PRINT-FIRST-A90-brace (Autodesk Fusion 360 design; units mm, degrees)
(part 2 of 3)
sketch "B Facet 180 Triangle 3" plane through (0, -75, 0) normal (0, -1, 0) x axis (-1, 0, 0)
  line L1 (60.9665, 27.066) -> (-2.067, -27.066)
  line L2 (124, -27.066) -> (60.9665, 27.066)
  line L3 (-2.067, -27.066) -> (124, -27.066)
  line L4 (60.9665, 21.7934) -> (8.7304, -23.066)
  line L5 (113.2026, -23.066) -> (60.9665, 21.7934)
  line L6 (8.7304, -23.066) -> (113.2026, -23.066)
  point P1 (0, 0)
  point P2 (-2.067, -27.066)
  point P3 (60.9665, 27.066)
  point P4 (124, -27.066)
  dimension "d477" distance P1 P2 = 2.067 (= "Linear Dimension-2")
  dimension "d478" distance P1 P2 = 27.066 (= "Linear Dimension-3")
  dimension "d479" distance P1 P3 = 60.9665 (= "Linear Dimension-4")
  dimension "d480" distance P1 P3 = 27.066 (= "Linear Dimension-5")
  dimension "d481" distance P1 P4 = 124 (= "Linear Dimension-6")
  dimension "d482" distance P1 P4 = 27.066 (= "Linear Dimension-7")
  dimension "d483" = 4 (= "memberWidth / 2")
extrude "Extrude14" cut sketch "B Facet 180 Triangle 3" profile of L5 L6 L4 against normal blind 4.7 (magnitude of "-( wall + 0.2 mm )")
sketch "B Facet 180 Triangle 4" plane through (0, -75, 0) normal (0, -1, 0) x axis (-1, 0, 0)
  line L1 (124, -27.066) -> (60.9665, 27.066)
  line L2 (124, 27.066) -> (124, -27.066)
  line L3 (60.9665, 27.066) -> (124, 27.066)
  line L4 (120, -18.3583) -> (71.7639, 23.066)
  line L5 (120, 23.066) -> (120, -18.3583)
  line L6 (71.7639, 23.066) -> (120, 23.066)
  point P1 (0, 0)
  point P2 (60.9665, 27.066)
  point P3 (124, -27.066)
  point P4 (124, 27.066)
  dimension "d486" distance P1 P2 = 60.9665 (= "Linear Dimension-2")
  dimension "d487" distance P1 P2 = 27.066 (= "Linear Dimension-3")
  dimension "d488" distance P1 P3 = 124 (= "Linear Dimension-4")
  dimension "d489" distance P1 P3 = 27.066 (= "Linear Dimension-5")
  dimension "d490" distance P1 P4 = 124 (= "Linear Dimension-6")
  dimension "d491" distance P1 P4 = 27.066 (= "Linear Dimension-7")
  dimension "d492" = -4 (= "-memberWidth / 2")
extrude "Extrude15" cut sketch "B Facet 180 Triangle 4" profile of L5 L6 L4 against normal blind 4.7 (magnitude of "-( wall + 0.2 mm )")
fillet "Fillet5" radius 1.5 (= "apertureRadius")
work_plane "WorkPlane11" RotateAngle 135 ExtraOffset 0
work_plane "WorkPlane12" AlongDistance 75 (= "bodyWidth / 2") ExtraOffset 0
sketch "B Facet 225 Triangle 1" plane through (0, -53.033, -53.033) normal (0, -0.7071, -0.7071) x axis (1, 0, 0)
  line L1 (23.9949, -27.066) -> (62.2721, 27.066)
  line L2 (0.1814, 27.066) -> (23.9949, -27.066)
  line L3 (62.2721, 27.066) -> (0.1814, 27.066)
  line L4 (24.81, -18.9852) -> (54.5447, 23.066)
  line L5 (6.311, 23.066) -> (24.81, -18.9852)
  line L6 (54.5447, 23.066) -> (6.311, 23.066)
  point P1 (0, 0)
  point P2 (62.2721, 27.066)
  point P3 (23.9949, -27.066)
  point P4 (0.1814, 27.066)
  dimension "d501" distance P1 P2 = 62.2721 (= "Linear Dimension-2")
  dimension "d502" distance P1 P2 = 27.066 (= "Linear Dimension-3")
  dimension "d503" distance P1 P3 = 23.9949 (= "Linear Dimension-4")
  dimension "d504" distance P1 P3 = 27.066 (= "Linear Dimension-5")
  dimension "d505" distance P1 P4 = 0.1814 (= "Linear Dimension-6")
  dimension "d506" distance P1 P4 = 27.066 (= "Linear Dimension-7")
  dimension "d507" = 4 (= "memberWidth / 2")
extrude "Extrude16" cut sketch "B Facet 225 Triangle 1" profile of L5 L6 L4 against normal blind 4.7 (magnitude of "-( wall + 0.2 mm )")
sketch "B Facet 225 Triangle 2" plane through (0, -53.033, -53.033) normal (0, -0.7071, -0.7071) x axis (1, 0, 0)
  line L1 (0.1814, 27.066) -> (23.9949, -27.066)
  line L2 (-74.6684, -27.066) -> (0.1814, 27.066)
  line L3 (23.9949, -27.066) -> (-74.6684, -27.066)
  line L4 (-1.4863, 20.9235) -> (17.8653, -23.066)
  line L5 (-62.3117, -23.066) -> (-1.4863, 20.9235)
  line L6 (17.8653, -23.066) -> (-62.3117, -23.066)
  point P1 (0, 0)
  point P2 (23.9949, -27.066)
  point P3 (0.1814, 27.066)
  point P4 (-74.6684, -27.066)
  dimension "d510" distance P1 P2 = 23.9949 (= "Linear Dimension-2")
  dimension "d511" distance P1 P2 = 27.066 (= "Linear Dimension-3")
  dimension "d512" distance P1 P3 = 0.1814 (= "Linear Dimension-4")
  dimension "d513" distance P1 P3 = 27.066 (= "Linear Dimension-5")
  dimension "d514" distance P1 P4 = 74.6684 (= "Linear Dimension-6")
  dimension "d515" distance P1 P4 = 27.066 (= "Linear Dimension-7")
  dimension "d516" = -4 (= "-memberWidth / 2")
extrude "Extrude17" cut sketch "B Facet 225 Triangle 2" profile of L5 L6 L4 against normal blind 4.7 (magnitude of "-( wall + 0.2 mm )")
sketch "B Facet 225 Triangle 3" plane through (0, -53.033, -53.033) normal (0, -0.7071, -0.7071) x axis (1, 0, 0)
  line L1 (-74.6684, -27.066) -> (0.1814, 27.066)
  line L2 (-124, 27.066) -> (-74.6684, -27.066)
  line L3 (0.1814, 27.066) -> (-124, 27.066)
  line L4 (-74.1179, -21.7315) -> (-12.1753, 23.066)
  line L5 (-114.9429, 23.066) -> (-74.1179, -21.7315)
  line L6 (-12.1753, 23.066) -> (-114.9429, 23.066)
  point P1 (0, 0)
  point P2 (0.1814, 27.066)
  point P3 (-74.6684, -27.066)
  point P4 (-124, 27.066)
  dimension "d519" distance P1 P2 = 0.1814 (= "Linear Dimension-2")
  dimension "d520" distance P1 P2 = 27.066 (= "Linear Dimension-3")
  dimension "d521" distance P1 P3 = 74.6684 (= "Linear Dimension-4")
  dimension "d522" distance P1 P3 = 27.066 (= "Linear Dimension-5")
  dimension "d523" distance P1 P4 = 124 (= "Linear Dimension-6")
  dimension "d524" distance P1 P4 = 27.066 (= "Linear Dimension-7")
  dimension "d525" = 4 (= "memberWidth / 2")
extrude "Extrude18" cut sketch "B Facet 225 Triangle 3" profile of L5 L6 L4 against normal blind 4.7 (magnitude of "-( wall + 0.2 mm )")
sketch "B Facet 225 Triangle 4" plane through (0, -53.033, -53.033) normal (0, -0.7071, -0.7071) x axis (1, 0, 0)
  line L1 (-124, 27.066) -> (-74.6684, -27.066)
  line L2 (-124, -27.066) -> (-124, 27.066)
  line L3 (-74.6684, -27.066) -> (-124, -27.066)
  line L4 (-120, 16.7383) -> (-83.7255, -23.066)
  line L5 (-120, -23.066) -> (-120, 16.7383)
  line L6 (-83.7255, -23.066) -> (-120, -23.066)
  point P1 (0, 0)
  point P2 (-74.6684, -27.066)
  point P3 (-124, 27.066)
  point P4 (-124, -27.066)
  dimension "d528" distance P1 P2 = 74.6684 (= "Linear Dimension-2")
  dimension "d529" distance P1 P2 = 27.066 (= "Linear Dimension-3")
  dimension "d530" distance P1 P3 = 124 (= "Linear Dimension-4")
  dimension "d531" distance P1 P3 = 27.066 (= "Linear Dimension-5")
  dimension "d532" distance P1 P4 = 124 (= "Linear Dimension-6")
  dimension "d533" distance P1 P4 = 27.066 (= "Linear Dimension-7")
  dimension "d534" = -4 (= "-memberWidth / 2")
extrude "Extrude19" cut sketch "B Facet 225 Triangle 4" profile of L5 L6 L4 against normal blind 4.7 (magnitude of "-( wall + 0.2 mm )")
fillet "Fillet6" radius 1.5 (= "apertureRadius")
work_plane "WorkPlane13" RotateAngle 180 ExtraOffset 0
work_plane "WorkPlane14" AlongDistance 75 (= "bodyWidth / 2") ExtraOffset 0
sketch "B Facet 270 Triangle 1" plane through (0, 0, -75) normal (0, 0, -1) x axis (-1, 0, 0)
  line L1 (36.9655, 27.066) -> (-17.1665, -27.066)
  line L2 (53.4167, -27.066) -> (36.9655, 27.066)
  line L3 (-17.1665, -27.066) -> (53.4167, -27.066)
  line L4 (35.0777, 19.5214) -> (-7.5097, -23.066)
  line L5 (48.0205, -23.066) -> (35.0777, 19.5214)
  line L6 (-7.5097, -23.066) -> (48.0205, -23.066)
  point P1 (0, 0)
  point P2 (-17.1665, -27.066)
  point P3 (36.9655, 27.066)
  point P4 (53.4167, -27.066)
  dimension "d543" distance P1 P2 = 17.1665 (= "Linear Dimension-2")
  dimension "d544" distance P1 P2 = 27.066 (= "Linear Dimension-3")
  dimension "d545" distance P1 P3 = 36.9655 (= "Linear Dimension-4")
  dimension "d546" distance P1 P3 = 27.066 (= "Linear Dimension-5")
  dimension "d547" distance P1 P4 = 53.4167 (= "Linear Dimension-6")
  dimension "d548" distance P1 P4 = 27.066 (= "Linear Dimension-7")
  dimension "d549" = 4 (= "memberWidth / 2")
extrude "Extrude20" cut sketch "B Facet 270 Triangle 1" profile of L5 L6 L4 against normal blind 4.7 (magnitude of "-( wall + 0.2 mm )")
sketch "B Facet 270 Triangle 2" plane through (0, 0, -75) normal (0, 0, -1) x axis (-1, 0, 0)
  line L1 (53.4167, -27.066) -> (36.9655, 27.066)
  line L2 (124, 27.066) -> (53.4167, -27.066)
  line L3 (36.9655, 27.066) -> (124, 27.066)
  line L4 (55.5648, -20.3777) -> (42.3618, 23.066)
  line L5 (112.2115, 23.066) -> (55.5648, -20.3777)
  line L6 (42.3618, 23.066) -> (112.2115, 23.066)
  point P1 (0, 0)
  point P2 (36.9655, 27.066)
  point P3 (53.4167, -27.066)
  point P4 (124, 27.066)
  dimension "d552" distance P1 P2 = 36.9655 (= "Linear Dimension-2")
  dimension "d553" distance P1 P2 = 27.066 (= "Linear Dimension-3")
  dimension "d554" distance P1 P3 = 53.4167 (= "Linear Dimension-4")
  dimension "d555" distance P1 P3 = 27.066 (= "Linear Dimension-5")
  dimension "d556" distance P1 P4 = 124 (= "Linear Dimension-6")
  dimension "d557" distance P1 P4 = 27.066 (= "Linear Dimension-7")
  dimension "d558" = -4 (= "-memberWidth / 2")
extrude "Extrude21" cut sketch "B Facet 270 Triangle 2" profile of L5 L6 L4 against normal blind 4.7 (magnitude of "-( wall + 0.2 mm )")
sketch "B Facet 270 Triangle 3" plane through (0, 0, -75) normal (0, 0, -1) x axis (-1, 0, 0)
  line L1 (124, 27.066) -> (53.4167, -27.066)
  line L2 (124, -27.066) -> (124, 27.066)
  line L3 (53.4167, -27.066) -> (124, -27.066)
  line L4 (120, 18.9574) -> (65.2053, -23.066)
  line L5 (120, -23.066) -> (120, 18.9574)
  line L6 (65.2053, -23.066) -> (120, -23.066)
  point P1 (0, 0)
  point P2 (53.4167, -27.066)
  point P3 (124, 27.066)
  point P4 (124, -27.066)
  dimension "d561" distance P1 P2 = 53.4167 (= "Linear Dimension-2")
  dimension "d562" distance P1 P2 = 27.066 (= "Linear Dimension-3")
  dimension "d563" distance P1 P3 = 124 (= "Linear Dimension-4")
  dimension "d564" distance P1 P3 = 27.066 (= "Linear Dimension-5")
  dimension "d565" distance P1 P4 = 124 (= "Linear Dimension-6")
  dimension "d566" distance P1 P4 = 27.066 (= "Linear Dimension-7")
  dimension "d567" = 4 (= "memberWidth / 2")
extrude "Extrude22" cut sketch "B Facet 270 Triangle 3" profile of L5 L6 L4 against normal blind 4.7 (magnitude of "-( wall + 0.2 mm )")
fillet "Fillet7" radius 1.5 (= "apertureRadius")
work_plane "WorkPlane15" RotateAngle 225 ExtraOffset 0
work_plane "WorkPlane16" AlongDistance 75 (= "bodyWidth / 2") ExtraOffset 0
sketch "B Facet 315 Triangle 1" plane through (0, 53.033, -53.033) normal (0, 0.7071, -0.7071) x axis (1, 0, 0)
  line L1 (-82.0711, -27.066) -> (-43.7939, 27.066)
  line L2 (-124, 27.066) -> (-82.0711, -27.066)
  line L3 (-43.7939, 27.066) -> (-124, 27.066)
  line L4 (-82.2175, -20.3449) -> (-51.5213, 23.066)
  line L5 (-115.8422, 23.066) -> (-82.2175, -20.3449)
  line L6 (-51.5213, 23.066) -> (-115.8422, 23.066)
  point P1 (0, 0)
  point P2 (-43.7939, 27.066)
  point P3 (-82.0711, -27.066)
  point P4 (-124, 27.066)
  dimension "d576" distance P1 P2 = 43.7939 (= "Linear Dimension-2")
  dimension "d577" distance P1 P2 = 27.066 (= "Linear Dimension-3")
  dimension "d578" distance P1 P3 = 82.0711 (= "Linear Dimension-4")
  dimension "d579" distance P1 P3 = 27.066 (= "Linear Dimension-5")
  dimension "d580" distance P1 P4 = 124 (= "Linear Dimension-6")
  dimension "d581" distance P1 P4 = 27.066 (= "Linear Dimension-7")
  dimension "d582" = 4 (= "memberWidth / 2")
extrude "Extrude23" cut sketch "B Facet 315 Triangle 1" profile of L5 L6 L4 against normal blind 4.7 (magnitude of "-( wall + 0.2 mm )")
sketch "B Facet 315 Triangle 2" plane through (0, 53.033, -53.033) normal (0, 0.7071, -0.7071) x axis (1, 0, 0)
  line L1 (-124, 27.066) -> (-82.0711, -27.066)
  line L2 (-124, -27.066) -> (-124, 27.066)
  line L3 (-82.0711, -27.066) -> (-124, -27.066)
  line L4 (-120, 15.3697) -> (-90.2289, -23.066)
  line L5 (-120, -23.066) -> (-120, 15.3697)
  line L6 (-90.2289, -23.066) -> (-120, -23.066)
  point P1 (0, 0)
  point P2 (-82.0711, -27.066)
  point P3 (-124, 27.066)
  point P4 (-124, -27.066)
  dimension "d585" distance P1 P2 = 82.0711 (= "Linear Dimension-2")
  dimension "d586" distance P1 P2 = 27.066 (= "Linear Dimension-3")
  dimension "d587" distance P1 P3 = 124 (= "Linear Dimension-4")
  dimension "d588" distance P1 P3 = 27.066 (= "Linear Dimension-5")
  dimension "d589" distance P1 P4 = 124 (= "Linear Dimension-6")
  dimension "d590" distance P1 P4 = 27.066 (= "Linear Dimension-7")
  dimension "d591" = -4 (= "-memberWidth / 2")
extrude "Extrude24" cut sketch "B Facet 315 Triangle 2" profile of L5 L6 L4 against normal blind 4.7 (magnitude of "-( wall + 0.2 mm )")
fillet "Fillet8" radius 1.5 (= "apertureRadius")
work_plane "WorkPlane17" AlongDistance 0.5 (= "qFront") ExtraOffset 0
sketch "A Central Carrier sketch" plane through (0.3536, 0.3536, 0) normal (0.7071, 0.7071, 0) x axis (0, 0, 1)
  circle C1 centre (0, 0) radius 26
  dimension "d598" diameter C1 = 52 (= "carrierOD")
extrude "Extrude25" new body sketch "A Central Carrier sketch" along normal blind 18 (= "spokeDepth")
work_plane "WorkPlane18" AlongDistance 0.5 (= "qFront") ExtraOffset 0
sketch "A Spoke 1 Profile" plane through (0.3536, 0.3536, 0) normal (0.7071, 0.7071, 0) x axis (0, 0, 1)
  line L1 (37.3643, -145.3579) -> (-4.7984, -1.4054)
  line L2 (46.9611, -142.547) -> (37.3643, -145.3579)
  line L3 (4.7984, 1.4054) -> (46.9611, -142.547)
  line L4 (-4.7984, -1.4054) -> (4.7984, 1.4054)
  point P1 (0, 0)
  point P2 (-4.7984, -1.4054)
  point P3 (37.3643, -145.3579)
  point P4 (46.9611, -142.547)
  point P5 (4.7984, 1.4054)
  dimension "d603" distance P1 P2 = 4.7984 (= "Linear Dimension-2")
  dimension "d604" distance P1 P2 = 1.4054 (= "Linear Dimension-3")
  dimension "d605" distance P1 P3 = 37.3643 (= "Linear Dimension-4")
  dimension "d606" distance P1 P3 = 145.3579 (= "Linear Dimension-5")
  dimension "d607" distance P1 P4 = 46.9611 (= "Linear Dimension-6")
  dimension "d608" distance P1 P4 = 142.547 (= "Linear Dimension-7")
  dimension "d609" distance P1 P5 = 4.7984 (= "Linear Dimension-8")
  dimension "d610" distance P1 P5 = 1.4054 (= "Linear Dimension-9")
extrude "Extrude26" add sketch "A Spoke 1 Profile" along normal blind 18 (= "spokeDepth")
sketch "A Spoke 2 Profile" plane through (0.3536, 0.3536, 0) normal (0.7071, 0.7071, 0) x axis (0, 0, 1)
  line L1 (126.9012, -80.1317) -> (-2.5272, -4.3143)
  line L2 (131.9557, -71.5031) -> (126.9012, -80.1317)
  line L3 (2.5272, 4.3143) -> (131.9557, -71.5031)
  line L4 (-2.5272, -4.3143) -> (2.5272, 4.3143)
  point P1 (0, 0)
  point P2 (-2.5272, -4.3143)
  point P3 (126.9012, -80.1317)
  point P4 (131.9557, -71.5031)
  point P5 (2.5272, 4.3143)
  dimension "d613" distance P1 P2 = 2.5272 (= "Linear Dimension-2")
  dimension "d614" distance P1 P2 = 4.3143 (= "Linear Dimension-3")
  dimension "d615" distance P1 P3 = 126.9012 (= "Linear Dimension-4")
  dimension "d616" distance P1 P3 = 80.1317 (= "Linear Dimension-5")
  dimension "d617" distance P1 P4 = 131.9557 (= "Linear Dimension-6")
  dimension "d618" distance P1 P4 = 71.5031 (= "Linear Dimension-7")
  dimension "d619" distance P1 P5 = 2.5272 (= "Linear Dimension-8")
  dimension "d620" distance P1 P5 = 4.3143 (= "Linear Dimension-9")
extrude "Extrude27" add sketch "A Spoke 2 Profile" along normal blind 18 (= "spokeDepth")
sketch "A Spoke 3 Profile" plane through (0.3536, 0.3536, 0) normal (0.7071, 0.7071, 0) x axis (0, 0, 1)
  line L1 (131.9557, 71.5031) -> (2.5272, -4.3143)
  line L2 (126.9012, 80.1317) -> (131.9557, 71.5031)
  line L3 (-2.5272, 4.3143) -> (126.9012, 80.1317)
  line L4 (2.5272, -4.3143) -> (-2.5272, 4.3143)
  point P1 (0, 0)
  point P2 (2.5272, -4.3143)
  point P3 (131.9557, 71.5031)
  point P4 (126.9012, 80.1317)
  point P5 (-2.5272, 4.3143)
  dimension "d623" distance P1 P2 = 2.5272 (= "Linear Dimension-2")
  dimension "d624" distance P1 P2 = 4.3143 (= "Linear Dimension-3")
  dimension "d625" distance P1 P3 = 131.9557 (= "Linear Dimension-4")
  dimension "d626" distance P1 P3 = 71.5031 (= "Linear Dimension-5")
  dimension "d627" distance P1 P4 = 126.9012 (= "Linear Dimension-6")
  dimension "d628" distance P1 P4 = 80.1317 (= "Linear Dimension-7")
  dimension "d629" distance P1 P5 = 2.5272 (= "Linear Dimension-8")
  dimension "d630" distance P1 P5 = 4.3143 (= "Linear Dimension-9")
extrude "Extrude28" add sketch "A Spoke 3 Profile" along normal blind 18 (= "spokeDepth")
sketch "A Spoke 4 Profile" plane through (0.3536, 0.3536, 0) normal (0.7071, 0.7071, 0) x axis (0, 0, 1)
  line L1 (46.9611, 142.547) -> (4.7984, -1.4054)
  line L2 (37.3643, 145.3579) -> (46.9611, 142.547)
  line L3 (-4.7984, 1.4054) -> (37.3643, 145.3579)
  line L4 (4.7984, -1.4054) -> (-4.7984, 1.4054)
  point P1 (0, 0)
  point P2 (4.7984, -1.4054)
  point P3 (46.9611, 142.547)
  point P4 (37.3643, 145.3579)
  point P5 (-4.7984, 1.4054)
  dimension "d633" distance P1 P2 = 4.7984 (= "Linear Dimension-2")
  dimension "d634" distance P1 P2 = 1.4054 (= "Linear Dimension-3")
  dimension "d635" distance P1 P3 = 46.9611 (= "Linear Dimension-4")
  dimension "d636" distance P1 P3 = 142.547 (= "Linear Dimension-5")
  dimension "d637" distance P1 P4 = 37.3643 (= "Linear Dimension-6")
  dimension "d638" distance P1 P4 = 145.3579 (= "Linear Dimension-7")
  dimension "d639" distance P1 P5 = 4.7984 (= "Linear Dimension-8")
  dimension "d640" distance P1 P5 = 1.4054 (= "Linear Dimension-9")
extrude "Extrude29" add sketch "A Spoke 4 Profile" along normal blind 18 (= "spokeDepth")
sketch "A Spoke 5 Profile" plane through (0.3536, 0.3536, 0) normal (0.7071, 0.7071, 0) x axis (0, 0, 1)
  line L1 (-37.3643, 145.3579) -> (4.7984, 1.4054)
  line L2 (-46.9611, 142.547) -> (-37.3643, 145.3579)
  line L3 (-4.7984, -1.4054) -> (-46.9611, 142.547)
  line L4 (4.7984, 1.4054) -> (-4.7984, -1.4054)
  point P1 (0, 0)
  point P2 (4.7984, 1.4054)
  point P3 (-37.3643, 145.3579)
  point P4 (-46.9611, 142.547)
  point P5 (-4.7984, -1.4054)
  dimension "d643" distance P1 P2 = 4.7984 (= "Linear Dimension-2")
  dimension "d644" distance P1 P2 = 1.4054 (= "Linear Dimension-3")
  dimension "d645" distance P1 P3 = 37.3643 (= "Linear Dimension-4")
  dimension "d646" distance P1 P3 = 145.3579 (= "Linear Dimension-5")
  dimension "d647" distance P1 P4 = 46.9611 (= "Linear Dimension-6")
  dimension "d648" distance P1 P4 = 142.547 (= "Linear Dimension-7")
  dimension "d649" distance P1 P5 = 4.7984 (= "Linear Dimension-8")
  dimension "d650" distance P1 P5 = 1.4054 (= "Linear Dimension-9")
extrude "Extrude30" add sketch "A Spoke 5 Profile" along normal blind 18 (= "spokeDepth")
sketch "A Spoke 6 Profile" plane through (0.3536, 0.3536, 0) normal (0.7071, 0.7071, 0) x axis (0, 0, 1)
  line L1 (-126.9012, 80.1317) -> (2.5272, 4.3143)
  line L2 (-131.9557, 71.5031) -> (-126.9012, 80.1317)
  line L3 (-2.5272, -4.3143) -> (-131.9557, 71.5031)
  line L4 (2.5272, 4.3143) -> (-2.5272, -4.3143)
  point P1 (0, 0)
  point P2 (2.5272, 4.3143)
  point P3 (-126.9012, 80.1317)
  point P4 (-131.9557, 71.5031)
  point P5 (-2.5272, -4.3143)
  dimension "d653" distance P1 P2 = 2.5272 (= "Linear Dimension-2")
  dimension "d654" distance P1 P2 = 4.3143 (= "Linear Dimension-3")
  dimension "d655" distance P1 P3 = 126.9012 (= "Linear Dimension-4")
  dimension "d656" distance P1 P3 = 80.1317 (= "Linear Dimension-5")
  dimension "d657" distance P1 P4 = 131.9557 (= "Linear Dimension-6")
  dimension "d658" distance P1 P4 = 71.5031 (= "Linear Dimension-7")
  dimension "d659" distance P1 P5 = 2.5272 (= "Linear Dimension-8")
  dimension "d660" distance P1 P5 = 4.3143 (= "Linear Dimension-9")
extrude "Extrude31" add sketch "A Spoke 6 Profile" along normal blind 18 (= "spokeDepth")
sketch "A Spoke 7 Profile" plane through (0.3536, 0.3536, 0) normal (0.7071, 0.7071, 0) x axis (0, 0, 1)
  line L1 (-131.9557, -71.5031) -> (-2.5272, 4.3143)
  line L2 (-126.9012, -80.1317) -> (-131.9557, -71.5031)
  line L3 (2.5272, -4.3143) -> (-126.9012, -80.1317)
  line L4 (-2.5272, 4.3143) -> (2.5272, -4.3143)
  point P1 (0, 0)
  point P2 (-2.5272, 4.3143)
  point P3 (-131.9557, -71.5031)
  point P4 (-126.9012, -80.1317)
  point P5 (2.5272, -4.3143)
  dimension "d663" distance P1 P2 = 2.5272 (= "Linear Dimension-2")
  dimension "d664" distance P1 P2 = 4.3143 (= "Linear Dimension-3")
  dimension "d665" distance P1 P3 = 131.9557 (= "Linear Dimension-4")
  dimension "d666" distance P1 P3 = 71.5031 (= "Linear Dimension-5")
  dimension "d667" distance P1 P4 = 126.9012 (= "Linear Dimension-6")
  dimension "d668" distance P1 P4 = 80.1317 (= "Linear Dimension-7")
  dimension "d669" distance P1 P5 = 2.5272 (= "Linear Dimension-8")
  dimension "d670" distance P1 P5 = 4.3143 (= "Linear Dimension-9")
extrude "Extrude32" add sketch "A Spoke 7 Profile" along normal blind 18 (= "spokeDepth")
sketch "A Spoke 8 Profile" plane through (0.3536, 0.3536, 0) normal (0.7071, 0.7071, 0) x axis (0, 0, 1)
  line L1 (-46.9611, -142.547) -> (-4.7984, 1.4054)
  line L2 (-37.3643, -145.3579) -> (-46.9611, -142.547)
  line L3 (4.7984, 1.4054) -> (-37.3643, -145.3579)
  line L4 (-4.7984, 1.4054) -> (4.7984, 1.4054)
  point P1 (0, 0)
  point P2 (-4.7984, 1.4054)
  point P3 (-46.9611, -142.547)
  point P4 (-37.3643, -145.3579)
  point P5 (4.7984, 1.4054)
  dimension "d673" distance P1 P2 = 4.7984 (= "Linear Dimension-2")
  dimension "d674" distance P1 P2 = 1.4054 (= "Linear Dimension-3")
  dimension "d675" distance P1 P3 = 46.9611 (= "Linear Dimension-4")
  dimension "d676" distance P1 P3 = 142.547 (= "Linear Dimension-5")
  dimension "d677" distance P1 P4 = 37.3643 (= "Linear Dimension-6")
  dimension "d678" distance P1 P4 = 145.3579 (= "Linear Dimension-7")
  dimension "d679" distance P1 P5 = 4.7984 (= "Linear Dimension-8")
  dimension "d680" distance P1 P5 = 1.4054 (= "Linear Dimension-9")
extrude "Extrude33" add sketch "A Spoke 8 Profile" along normal blind 18 (= "spokeDepth")
sketch "Spoke Outer Envelope" plane through (0, 0, 0) normal (1, 0, 0) x axis (0, 0, -1)
  line L1 (31.066, 75) -> (75, 31.066)
  line L2 (-31.066, 75) -> (31.066, 75)
  line L3 (-75, 31.066) -> (-31.066, 75)
  line L4 (-75, -31.066) -> (-75, 31.066)
  line L5 (-31.066, -75) -> (-75, -31.066)
  line L6 (31.066, -75) -> (-31.066, -75)
  line L7 (75, -31.066) -> (31.066, -75)
  line L8 (75, 31.066) -> (75, -31.066)
  point P1 (0, 0)
  point P10 (0, 0)
  point P3 (31.066, 75)
  point P8 (31.066, -75)
  coincident P1 P10
  horizontal L2
  dimension "d683" distance P3 P8 = 150 (= "bodyWidth")
extrude "Extrude34" sketch "Spoke Outer Envelope" distance 260 (= "bodyLength")
fillet "Fillet9" radius 1 (= "rootRadius")
work_plane "WorkPlane19" AlongDistance 10.6 (= "qFrontBack") ExtraOffset 0
sketch "A Rear Carrier Clearance sketch" plane through (7.4953, 7.4953, 0) normal (0.7071, 0.7071, 0) x axis (0, 0, 1)
  circle C1 centre (0, 0) radius 23
  dimension "d690" diameter C1 = 46 (= "rearCarrierClearance")
extrude "Extrude35" cut sketch "A Rear Carrier Clearance sketch" along normal blind 18 (= "spokeDepth")
work_plane "WorkPlane20" AlongDistance 0.5 (= "qFront") ExtraOffset 0
sketch "A Seal Relief sketch" plane through (0.3536, 0.3536, 0) normal (0.7071, 0.7071, 0) x axis (0, 0, 1)
  circle C1 centre (0, 0) radius 9.75
  dimension "d695" diameter C1 = 19.5 (= "raceRelief")
extrude "Extrude36" cut sketch "A Seal Relief sketch" along normal blind 10.1 (= "frontSeatDepth + shoulder")
work_plane "WorkPlane21" AlongDistance 0.5 (= "qFront") ExtraOffset 0
sketch "A Front Bearing Seat sketch" plane through (0.3536, 0.3536, 0) normal (0.7071, 0.7071, 0) x axis (0, 0, 1)
  circle C1 centre (0, 0) radius 11.1
  dimension "d700" diameter C1 = 22.2 (= "seatDiameter")
extrude "Extrude37" cut sketch "A Front Bearing Seat sketch" along normal blind 7.1 (= "frontSeatDepth")
work_plane "WorkPlane22" AlongDistance 0.5 (= "qFront") ExtraOffset 0
sketch "A Support Bolt seed" plane through (0.3536, 0.3536, 0) normal (0.7071, 0.7071, 0) x axis (0, 0, 1)
  line L1 (17, 0) -> (0, 0)
  circle C1 centre (17, 0) radius 1.65
  point P1 (0, 0)
  point P2 (17, 0)
  horizontal L1
  dimension "d705" distance P1 P2 = 17 (= "supportCircle / 2")
  dimension "d706" diameter C1 = 3.3 (= "m3Clearance")
extrude "Extrude38" cut sketch "A Support Bolt seed" profile of C1 along normal blind 10.1 (= "frontSeatDepth + shoulder")
circular_pattern "C-Pattern1" TotalAngle 360
work_plane "WorkPlane23" AlongDistance 0.5 (= "qFront") ExtraOffset 0
sketch "A Front Bearing Boss sketch" plane through (0.3536, 0.3536, 0) normal (0.7071, 0.7071, 0) x axis (0, 0, 1)
  circle C1 centre (0, 0) radius 22
  dimension "d713" diameter C1 = 44 (= "coreOD")
chamfer "Chamfer1" distance 0.4 (= "entryChamfer")
work_plane "WorkPlane24" AlongDistance 75 (= "bodyWidth / 2") ExtraOffset 0
sketch "A Collar Driver Corridors" plane through (0, 0, 75) normal (0, 0, 1) x axis (1, 0, 0)
  circle C1 centre (6.7175, 15.9099) radius 3
  circle C2 centre (15.9099, 6.7175) radius 3
  point P1 (0, 0)
  point P2 (6.7175, 15.9099)
  point P3 (15.9099, 6.7175)
  dimension "d717" distance P1 P2 = 6.7175 (= "abs(( 16 mm + ( -6.5 mm ) ) / sqrt(2))")
  dimension "d718" distance P1 P2 = 15.9099 (= "abs(( 16 mm - ( -6.5 mm ) ) / sqrt(2))")
  dimension "d719" diameter C1 = 6
  dimension "d720" distance P1 P3 = 15.9099 (= "abs(( 16 mm + ( 6.5 mm ) ) / sqrt(2))")
  dimension "d721" distance P1 P3 = 6.7175 (= "abs(( 16 mm - ( 6.5 mm ) ) / sqrt(2))")
  dimension "d722" diameter C2 = 6
extrude "Extrude39" cut sketch "A Collar Driver Corridors" against normal blind 75 (magnitude of "-( bodyWidth / 2 )")
work_plane "WorkPlane17" ExtraOffset 0
sketch "B Central Carrier sketch" plane through (-0.3536, -0.3536, 0) normal (0.7071, 0.7071, 0) x axis (0, 0, 1)
  circle C1 centre (0, 0) radius 38
  dimension "d727" diameter C1 = 76 (= "mountOD")
extrude "Extrude25" new body sketch "B Central Carrier sketch" no distance stored
work_plane "WorkPlane18" ExtraOffset 0
sketch "B Spoke 1 Profile" plane through (-0.3536, -0.3536, 0) normal (0.7071, 0.7071, 0) x axis (0, 0, 1)
  line L1 (37.3643, -145.3579) -> (-4.7984, -1.4054)
  line L2 (46.9611, -142.547) -> (37.3643, -145.3579)
  line L3 (4.7984, 1.4054) -> (46.9611, -142.547)
  line L4 (-4.7984, -1.4054) -> (4.7984, 1.4054)
  point P1 (0, 0)
  point P2 (-4.7984, -1.4054)
  point P3 (37.3643, -145.3579)
  point P4 (46.9611, -142.547)
  point P5 (4.7984, 1.4054)
  dimension "d732" distance P1 P2 = 4.7984 (= "Linear Dimension-2")
  dimension "d733" distance P1 P2 = 1.4054 (= "Linear Dimension-3")
  dimension "d734" distance P1 P3 = 37.3643 (= "Linear Dimension-4")
  dimension "d735" distance P1 P3 = 145.3579 (= "Linear Dimension-5")
  dimension "d736" distance P1 P4 = 46.9611 (= "Linear Dimension-6")
  dimension "d737" distance P1 P4 = 142.547 (= "Linear Dimension-7")
  dimension "d738" distance P1 P5 = 4.7984 (= "Linear Dimension-8")
  dimension "d739" distance P1 P5 = 1.4054 (= "Linear Dimension-9")
extrude "Extrude26" add sketch "B Spoke 1 Profile" no distance stored
sketch "B Spoke 2 Profile" plane through (-0.3536, -0.3536, 0) normal (0.7071, 0.7071, 0) x axis (0, 0, 1)
  line L1 (126.9012, -80.1317) -> (-2.5272, -4.3143)
  line L2 (131.9557, -71.5031) -> (126.9012, -80.1317)
  line L3 (2.5272, 4.3143) -> (131.9557, -71.5031)
  line L4 (-2.5272, -4.3143) -> (2.5272, 4.3143)
  point P1 (0, 0)
  point P2 (-2.5272, -4.3143)
  point P3 (126.9012, -80.1317)
  point P4 (131.9557, -71.5031)
  point P5 (2.5272, 4.3143)
  dimension "d742" distance P1 P2 = 2.5272 (= "Linear Dimension-2")
  dimension "d743" distance P1 P2 = 4.3143 (= "Linear Dimension-3")
  dimension "d744" distance P1 P3 = 126.9012 (= "Linear Dimension-4")
  dimension "d745" distance P1 P3 = 80.1317 (= "Linear Dimension-5")
  dimension "d746" distance P1 P4 = 131.9557 (= "Linear Dimension-6")
  dimension "d747" distance P1 P4 = 71.5031 (= "Linear Dimension-7")
  dimension "d748" distance P1 P5 = 2.5272 (= "Linear Dimension-8")
  dimension "d749" distance P1 P5 = 4.3143 (= "Linear Dimension-9")
extrude "Extrude27" add sketch "B Spoke 2 Profile" no distance stored
sketch "B Spoke 3 Profile" plane through (-0.3536, -0.3536, 0) normal (0.7071, 0.7071, 0) x axis (0, 0, 1)
  line L1 (131.9557, 71.5031) -> (2.5272, -4.3143)
  line L2 (126.9012, 80.1317) -> (131.9557, 71.5031)
  line L3 (-2.5272, 4.3143) -> (126.9012, 80.1317)
  line L4 (2.5272, -4.3143) -> (-2.5272, 4.3143)
  point P1 (0, 0)
  point P2 (2.5272, -4.3143)
  point P3 (131.9557, 71.5031)
  point P4 (126.9012, 80.1317)
  point P5 (-2.5272, 4.3143)
  dimension "d752" distance P1 P2 = 2.5272 (= "Linear Dimension-2")
  dimension "d753" distance P1 P2 = 4.3143 (= "Linear Dimension-3")
  dimension "d754" distance P1 P3 = 131.9557 (= "Linear Dimension-4")
  dimension "d755" distance P1 P3 = 71.5031 (= "Linear Dimension-5")
  dimension "d756" distance P1 P4 = 126.9012 (= "Linear Dimension-6")
  dimension "d757" distance P1 P4 = 80.1317 (= "Linear Dimension-7")
  dimension "d758" distance P1 P5 = 2.5272 (= "Linear Dimension-8")
  dimension "d759" distance P1 P5 = 4.3143 (= "Linear Dimension-9")
extrude "Extrude28" add sketch "B Spoke 3 Profile" no distance stored
sketch "B Spoke 4 Profile" plane through (-0.3536, -0.3536, 0) normal (0.7071, 0.7071, 0) x axis (0, 0, 1)
  line L1 (46.9611, 142.547) -> (4.7984, -1.4054)
  line L2 (37.3643, 145.3579) -> (46.9611, 142.547)
  line L3 (-4.7984, 1.4054) -> (37.3643, 145.3579)
  line L4 (4.7984, -1.4054) -> (-4.7984, 1.4054)
  point P1 (0, 0)
  point P2 (4.7984, -1.4054)
  point P3 (46.9611, 142.547)
  point P4 (37.3643, 145.3579)
  point P5 (-4.7984, 1.4054)
  dimension "d762" distance P1 P2 = 4.7984 (= "Linear Dimension-2")
  dimension "d763" distance P1 P2 = 1.4054 (= "Linear Dimension-3")
  dimension "d764" distance P1 P3 = 46.9611 (= "Linear Dimension-4")
  dimension "d765" distance P1 P3 = 142.547 (= "Linear Dimension-5")
  dimension "d766" distance P1 P4 = 37.3643 (= "Linear Dimension-6")
  dimension "d767" distance P1 P4 = 145.3579 (= "Linear Dimension-7")
  dimension "d768" distance P1 P5 = 4.7984 (= "Linear Dimension-8")
  dimension "d769" distance P1 P5 = 1.4054 (= "Linear Dimension-9")
extrude "Extrude29" add sketch "B Spoke 4 Profile" no distance stored
sketch "B Spoke 5 Profile" plane through (-0.3536, -0.3536, 0) normal (0.7071, 0.7071, 0) x axis (0, 0, 1)
  line L1 (-37.3643, 145.3579) -> (4.7984, 1.4054)
  line L2 (-46.9611, 142.547) -> (-37.3643, 145.3579)
  line L3 (-4.7984, -1.4054) -> (-46.9611, 142.547)
  line L4 (4.7984, 1.4054) -> (-4.7984, -1.4054)
  point P1 (0, 0)
  point P2 (4.7984, 1.4054)
  point P3 (-37.3643, 145.3579)
  point P4 (-46.9611, 142.547)
  point P5 (-4.7984, -1.4054)
  dimension "d772" distance P1 P2 = 4.7984 (= "Linear Dimension-2")
  dimension "d773" distance P1 P2 = 1.4054 (= "Linear Dimension-3")
  dimension "d774" distance P1 P3 = 37.3643 (= "Linear Dimension-4")
  dimension "d775" distance P1 P3 = 145.3579 (= "Linear Dimension-5")
  dimension "d776" distance P1 P4 = 46.9611 (= "Linear Dimension-6")
  dimension "d777" distance P1 P4 = 142.547 (= "Linear Dimension-7")
  dimension "d778" distance P1 P5 = 4.7984 (= "Linear Dimension-8")
  dimension "d779" distance P1 P5 = 1.4054 (= "Linear Dimension-9")
extrude "Extrude30" add sketch "B Spoke 5 Profile" no distance stored
sketch "B Spoke 6 Profile" plane through (-0.3536, -0.3536, 0) normal (0.7071, 0.7071, 0) x axis (0, 0, 1)
  line L1 (-126.9012, 80.1317) -> (2.5272, 4.3143)
  line L2 (-131.9557, 71.5031) -> (-126.9012, 80.1317)
  line L3 (-2.5272, -4.3143) -> (-131.9557, 71.5031)
  line L4 (2.5272, 4.3143) -> (-2.5272, -4.3143)
  point P1 (0, 0)
  point P2 (2.5272, 4.3143)
  point P3 (-126.9012, 80.1317)
  point P4 (-131.9557, 71.5031)
  point P5 (-2.5272, -4.3143)
  dimension "d782" distance P1 P2 = 2.5272 (= "Linear Dimension-2")
  dimension "d783" distance P1 P2 = 4.3143 (= "Linear Dimension-3")
  dimension "d784" distance P1 P3 = 126.9012 (= "Linear Dimension-4")
  dimension "d785" distance P1 P3 = 80.1317 (= "Linear Dimension-5")
  dimension "d786" distance P1 P4 = 131.9557 (= "Linear Dimension-6")
  dimension "d787" distance P1 P4 = 71.5031 (= "Linear Dimension-7")
  dimension "d788" distance P1 P5 = 2.5272 (= "Linear Dimension-8")
  dimension "d789" distance P1 P5 = 4.3143 (= "Linear Dimension-9")
extrude "Extrude31" add sketch "B Spoke 6 Profile" no distance stored
sketch "B Spoke 7 Profile" plane through (-0.3536, -0.3536, 0) normal (0.7071, 0.7071, 0) x axis (0, 0, 1)
  line L1 (-131.9557, -71.5031) -> (-2.5272, 4.3143)
  line L2 (-126.9012, -80.1317) -> (-131.9557, -71.5031)
  line L3 (2.5272, -4.3143) -> (-126.9012, -80.1317)
  line L4 (-2.5272, 4.3143) -> (2.5272, -4.3143)
  point P1 (0, 0)
  point P2 (-2.5272, 4.3143)
  point P3 (-131.9557, -71.5031)
  point P4 (-126.9012, -80.1317)
  point P5 (2.5272, -4.3143)
  dimension "d792" distance P1 P2 = 2.5272 (= "Linear Dimension-2")
  dimension "d793" distance P1 P2 = 4.3143 (= "Linear Dimension-3")
  dimension "d794" distance P1 P3 = 131.9557 (= "Linear Dimension-4")
  dimension "d795" distance P1 P3 = 71.5031 (= "Linear Dimension-5")
  dimension "d796" distance P1 P4 = 126.9012 (= "Linear Dimension-6")
  dimension "d797" distance P1 P4 = 80.1317 (= "Linear Dimension-7")
  dimension "d798" distance P1 P5 = 2.5272 (= "Linear Dimension-8")
  dimension "d799" distance P1 P5 = 4.3143 (= "Linear Dimension-9")
extrude "Extrude32" add sketch "B Spoke 7 Profile" no distance stored
sketch "B Spoke 8 Profile" plane through (-0.3536, -0.3536, 0) normal (0.7071, 0.7071, 0) x axis (0, 0, 1)
  line L1 (-46.9611, -142.547) -> (-4.7984, 1.4054)
  line L2 (-37.3643, -145.3579) -> (-46.9611, -142.547)
  line L3 (4.7984, 1.4054) -> (-37.3643, -145.3579)
  line L4 (-4.7984, 1.4054) -> (4.7984, 1.4054)
  point P1 (0, 0)
  point P2 (-4.7984, 1.4054)
  point P3 (-46.9611, -142.547)
  point P4 (-37.3643, -145.3579)
  point P5 (4.7984, 1.4054)
  dimension "d802" distance P1 P2 = 4.7984 (= "Linear Dimension-2")
  dimension "d803" distance P1 P2 = 1.4054 (= "Linear Dimension-3")
  dimension "d804" distance P1 P3 = 46.9611 (= "Linear Dimension-4")
  dimension "d805" distance P1 P3 = 142.547 (= "Linear Dimension-5")
  dimension "d806" distance P1 P4 = 37.3643 (= "Linear Dimension-6")
  dimension "d807" distance P1 P4 = 145.3579 (= "Linear Dimension-7")
  dimension "d808" distance P1 P5 = 4.7984 (= "Linear Dimension-8")
  dimension "d809" distance P1 P5 = 1.4054 (= "Linear Dimension-9")
extrude "Extrude33" add sketch "B Spoke 8 Profile" no distance stored
sketch "Spoke Outer Envelope" plane through (0, 0, 0) normal (1, 0, 0) x axis (0, 0, -1)
  line L1 (31.066, 75) -> (75, 31.066)
  line L2 (-31.066, 75) -> (31.066, 75)
  line L3 (-75, 31.066) -> (-31.066, 75)
  line L4 (-75, -31.066) -> (-75, 31.066)
  line L5 (-31.066, -75) -> (-75, -31.066)
  line L6 (31.066, -75) -> (-31.066, -75)
  line L7 (75, -31.066) -> (31.066, -75)
  line L8 (75, 31.066) -> (75, -31.066)
  point P1 (0, 0)
  point P10 (0, 0)
  point P3 (31.066, 75)
  point P8 (31.066, -75)
  coincident P1 P10
  horizontal L2
  dimension "d812" distance P3 P8 = 150 (= "bodyWidth")
extrude "Extrude34" sketch "Spoke Outer Envelope" distance 260 (= "bodyLength")
fillet "Fillet9" radius 1 (= "rootRadius")
work_plane "WorkPlane19" ExtraOffset 0
sketch "B Open Hub Cavity sketch" plane through (-0.3536, -0.3536, 0) normal (0.7071, 0.7071, 0) x axis (0, 0, 1)
  circle C1 centre (0, 0) radius 25.15
  dimension "d819" diameter C1 = 50.3 (= "mountOpening")
extrude "Extrude35" cut sketch "B Open Hub Cavity sketch" no distance stored
work_plane "WorkPlane20" ExtraOffset 0
sketch "B Four Mount Holes" plane through (-0.3536, -0.3536, 0) normal (0.7071, 0.7071, 0) x axis (0, 0, 1)
  circle C1 centre (22.6274, 22.6274) radius 2.15
  circle C2 centre (-22.6274, 22.6274) radius 2.15
  circle C3 centre (-22.6274, -22.6274) radius 2.15
  circle C4 centre (22.6274, -22.6274) radius 2.15
  point P1 (0, 0)
  point P2 (22.6274, 22.6274)
  point P3 (-22.6274, 22.6274)
  point P4 (-22.6274, -22.6274)
  point P5 (22.6274, -22.6274)
  dimension "d824" distance P1 P2 = 22.6274 (= "abs(mountCircle / ( 2 * sqrt(2) ))")
  dimension "d825" distance P1 P2 = 22.6274 (= "abs(mountCircle / ( 2 * sqrt(2) ))")
  dimension "d826" diameter C1 = 4.3 (= "m4Clearance")
  dimension "d827" distance P1 P3 = 22.6274 (= "abs(-mountCircle / ( 2 * sqrt(2) ))")
  dimension "d828" distance P1 P3 = 22.6274 (= "abs(mountCircle / ( 2 * sqrt(2) ))")
  dimension "d829" diameter C2 = 4.3 (= "m4Clearance")
  dimension "d830" distance P1 P4 = 22.6274 (= "abs(-mountCircle / ( 2 * sqrt(2) ))")
  dimension "d831" distance P1 P4 = 22.6274 (= "abs(-mountCircle / ( 2 * sqrt(2) ))")
  dimension "d832" diameter C3 = 4.3 (= "m4Clearance")
  dimension "d833" distance P1 P5 = 22.6274 (= "abs(mountCircle / ( 2 * sqrt(2) ))")
  dimension "d834" distance P1 P5 = 22.6274 (= "abs(-mountCircle / ( 2 * sqrt(2) ))")
  dimension "d835" diameter C4 = 4.3 (= "m4Clearance")
extrude "Extrude36" cut sketch "B Four Mount Holes" no distance stored
sketch "B M4 Nut Pocket 1" plane through (-0.3536, -0.3536, 0) normal (0.7071, 0.7071, 0) x axis (0, 0, 1)
  line L1 (24.7059, 26.2274) -> (26.7843, 22.6274)
  line L2 (20.549, 26.2274) -> (24.7059, 26.2274)
  line L3 (18.4705, 22.6274) -> (20.549, 26.2274)
  line L4 (20.549, 19.0274) -> (18.4705, 22.6274)
  line L5 (24.7059, 19.0274) -> (20.549, 19.0274)
  line L6 (26.7843, 22.6274) -> (24.7059, 19.0274)
  circle C1 centre (22.6274, 22.6274) radius 4.1569
  point P3 (26.7843, 22.6274)
  point P4 (24.7059, 26.2274)
  point P5 (20.549, 26.2274)
  point P6 (18.4705, 22.6274)
  point P7 (20.549, 19.0274)
  point P8 (24.7059, 19.0274)
  point P1 (0, 0)
  point P2 (22.6274, 22.6274)
  coincident C1 P3
  coincident C1 P4
  coincident C1 P5
  coincident C1 P6
  coincident C1 P7
  coincident C1 P8
  equal L1 L2
  equal L1 L3
  equal L1 L4
  equal L1 L5
  equal L1 L6
  horizontal L2
  dimension "d838" distance P1 P2 = 22.6274 (= "abs(mountCircle / ( 2 * sqrt(2) ))")
  dimension "d839" distance P1 P2 = 22.6274 (= "abs(mountCircle / ( 2 * sqrt(2) ))")
  dimension "d840" diameter C1 = 8.3138 (= "2 * ( nutAF ) / sqrt(3)")
extrude "Extrude37" cut sketch "B M4 Nut Pocket 1" profile of L1 L2 L3 L4 L5 L6 no distance stored
sketch "B M4 Nut Pocket 2" plane through (-0.3536, -0.3536, 0) normal (0.7071, 0.7071, 0) x axis (0, 0, 1)
  line L1 (-20.549, 26.2274) -> (-18.4705, 22.6274)
  line L2 (-24.7059, 26.2274) -> (-20.549, 26.2274)
  line L3 (-26.7843, 22.6274) -> (-24.7059, 26.2274)
  line L4 (-24.7059, 19.0274) -> (-26.7843, 22.6274)
  line L5 (-20.549, 19.0274) -> (-24.7059, 19.0274)
  line L6 (-18.4705, 22.6274) -> (-20.549, 19.0274)
  circle C1 centre (-22.6274, 22.6274) radius 4.1569
  point P3 (-18.4705, 22.6274)
  point P4 (-20.549, 26.2274)
  point P5 (-24.7059, 26.2274)
  point P6 (-26.7843, 22.6274)
  point P7 (-24.7059, 19.0274)
  point P8 (-20.549, 19.0274)
  point P1 (0, 0)
  point P2 (-22.6274, 22.6274)
  coincident C1 P3
  coincident C1 P4
  coincident C1 P5
  coincident C1 P6
  coincident C1 P7
  coincident C1 P8
  equal L1 L2
  equal L1 L3
  equal L1 L4
  equal L1 L5
  equal L1 L6
  horizontal L2
  dimension "d843" distance P1 P2 = 22.6274 (= "abs(-mountCircle / ( 2 * sqrt(2) ))")
  dimension "d844" distance P1 P2 = 22.6274 (= "abs(mountCircle / ( 2 * sqrt(2) ))")
  dimension "d845" diameter C1 = 8.3138 (= "2 * ( nutAF ) / sqrt(3)")
extrude "Extrude38" cut sketch "B M4 Nut Pocket 2" profile of L1 L2 L3 L4 L5 L6 no distance stored
sketch "B M4 Nut Pocket 3" plane through (-0.3536, -0.3536, 0) normal (0.7071, 0.7071, 0) x axis (0, 0, 1)
  line L1 (-20.549, -19.0274) -> (-18.4705, -22.6274)
  line L2 (-24.7059, -19.0274) -> (-20.549, -19.0274)
  line L3 (-26.7843, -22.6274) -> (-24.7059, -19.0274)
  line L4 (-24.7059, -26.2274) -> (-26.7843, -22.6274)
  line L5 (-20.549, -26.2274) -> (-24.7059, -26.2274)
  line L6 (-18.4705, -22.6274) -> (-20.549, -26.2274)
  circle C1 centre (-22.6274, -22.6274) radius 4.1569
  point P3 (-18.4705, -22.6274)
  point P4 (-20.549, -19.0274)
  point P5 (-24.7059, -19.0274)
  point P6 (-26.7843, -22.6274)
  point P7 (-24.7059, -26.2274)
  point P8 (-20.549, -26.2274)
  point P1 (0, 0)
  point P2 (-22.6274, -22.6274)
  coincident C1 P3
  coincident C1 P4
  coincident C1 P5
  coincident C1 P6
  coincident C1 P7
  coincident C1 P8
  equal L1 L2
  equal L1 L3
  equal L1 L4
  equal L1 L5
  equal L1 L6
  horizontal L2
  dimension "d848" distance P1 P2 = 22.6274 (= "abs(-mountCircle / ( 2 * sqrt(2) ))")
  dimension "d849" distance P1 P2 = 22.6274 (= "abs(-mountCircle / ( 2 * sqrt(2) ))")
  dimension "d850" diameter C1 = 8.3138 (= "2 * ( nutAF ) / sqrt(3)")
extrude "Extrude39" cut sketch "B M4 Nut Pocket 3" profile of L1 L2 L3 L4 L5 L6 no distance stored
sketch "B M4 Nut Pocket 4" plane through (-0.3536, -0.3536, 0) normal (0.7071, 0.7071, 0) x axis (0, 0, 1)
  line L1 (24.7059, -19.0274) -> (26.7843, -22.6274)
  line L2 (20.549, -19.0274) -> (24.7059, -19.0274)
  line L3 (18.4705, -22.6274) -> (20.549, -19.0274)
  line L4 (20.549, -26.2274) -> (18.4705, -22.6274)
  line L5 (24.7059, -26.2274) -> (20.549, -26.2274)
  line L6 (26.7843, -22.6274) -> (24.7059, -26.2274)
  circle C1 centre (22.6274, -22.6274) radius 4.1569
  point P3 (26.7843, -22.6274)
  point P4 (24.7059, -19.0274)
  point P5 (20.549, -19.0274)
  point P6 (18.4705, -22.6274)
  point P7 (20.549, -26.2274)
  point P8 (24.7059, -26.2274)
  point P1 (0, 0)
  point P2 (22.6274, -22.6274)
  coincident C1 P3
  coincident C1 P4
  coincident C1 P5
  coincident C1 P6
  coincident C1 P7
  coincident C1 P8
  equal L1 L2
  equal L1 L3
  equal L1 L4
  equal L1 L5
  equal L1 L6
  horizontal L2
  dimension "d853" distance P1 P2 = 22.6274 (= "abs(mountCircle / ( 2 * sqrt(2) ))")
  dimension "d854" distance P1 P2 = 22.6274 (= "abs(-mountCircle / ( 2 * sqrt(2) ))")
  dimension "d855" diameter C1 = 8.3138 (= "2 * ( nutAF ) / sqrt(3)")
extrude "Extrude40" cut sketch "B M4 Nut Pocket 4" profile of L1 L2 L3 L4 L5 L6 no distance stored
sketch "B Hub Service Slots" plane through (0, 0, 0) normal (0, 0, 1) x axis (1, 0, 0)
  line L1 (-30.4056, -12.0208) -> (-14.8492, 3.5355)
  line L2 (-12.0208, -30.4056) -> (-30.4056, -12.0208)
  line L3 (3.5355, -14.8492) -> (-12.0208, -30.4056)
  line L4 (-14.8492, 3.5355) -> (3.5355, -14.8492)
  point P1 (0, 0)
  point P2 (-14.8492, 3.5355)
  point P3 (-30.4056, -12.0208)
  point P4 (-12.0208, -30.4056)
  point P5 (3.5355, -14.8492)
  dimension "d858" distance P1 P2 = 14.8492 (= "abs(( -8 mm - 13 mm ) / sqrt(2))")
  dimension "d859" distance P1 P2 = 3.5355 (= "abs(( -8 mm + 13 mm ) / sqrt(2))")
  dimension "d860" distance P1 P3 = 30.4056 (= "abs(( -30 mm - 13 mm ) / sqrt(2))")
  dimension "d861" distance P1 P3 = 12.0208 (= "abs(( -30 mm + 13 mm ) / sqrt(2))")
  dimension "d862" distance P1 P4 = 12.0208 (= "abs(( -30 mm + 13 mm ) / sqrt(2))")
  dimension "d863" distance P1 P4 = 30.4056 (= "abs(( -30 mm - 13 mm ) / sqrt(2))")
  dimension "d864" distance P1 P5 = 3.5355 (= "abs(( -8 mm + 13 mm ) / sqrt(2))")
  dimension "d865" distance P1 P5 = 14.8492 (= "abs(( -8 mm - 13 mm ) / sqrt(2))")
extrude "Extrude41" cut sketch "B Hub Service Slots" distance 76 (= "mountOD")
chamfer "Chamfer2" distance 0.3 (= "bedRelief")
chamfer "Chamfer3" distance 0.5 (= "tubeCornerChamfer")
chamfer "Chamfer4" sketch "A Facet 135 Triangle 1" distance 0.3 (= "tubeRimChamfer")
work_plane "WorkPlane25" RotateAngle 0 ExtraOffset 0
work_plane "WorkPlane26" AlongDistance 75 (= "bodyWidth / 2") ExtraOffset 0
sketch "A End Cord Port" plane through (0, 0, 75) normal (0, 0, 1) x axis (1, 0, 0)
  line L1 (125, 0) -> (0, 0)
  circle C1 centre (125, 0) radius 2.25
  point P1 (0, 0)
  point P2 (125, 0)
  horizontal L1
  dimension "d875" distance P1 P2 = 125 (= "abs(( 1 ) * ( ( 1 ) * cordStation ) + ( 0 ) * ( 0 mm ))")
  dimension "d876" diameter C1 = 4.5
extrude "Extrude40" cut sketch "A End Cord Port" profile of C1 no distance stored
chamfer "Chamfer5" distance 0.3 (= "bedRelief")
work_plane "WorkPlane27" RotateAngle 180 ExtraOffset 0
work_plane "WorkPlane28" AlongDistance 75 (= "bodyWidth / 2") ExtraOffset 0
sketch "A End Cord Port (1)" plane through (0, 0, -75) normal (0, 0, -1) x axis (-1, 0, 0)
  line L1 (-125, 0) -> (0, 0)
  circle C1 centre (-125, 0) radius 2.25
  point P1 (0, 0)
  point P2 (-125, 0)
  horizontal L1
  dimension "d884" distance P1 P2 = 125 (= "abs(( -1 ) * ( ( 1 ) * cordStation ) + ( 0 ) * ( 0 mm ))")
  dimension "d885" diameter C1 = 4.5
extrude "Extrude41" cut sketch "A End Cord Port (1)" profile of C1 no distance stored
chamfer "Chamfer6" distance 0.3 (= "bedRelief")
chamfer "Chamfer1" distance 0.3 (= "bedRelief")
chamfer "Chamfer2" distance 0.5 (= "tubeCornerChamfer")
chamfer "Chamfer3" sketch "A Facet 135 Triangle 1" distance 0.3 (= "tubeRimChamfer")
work_plane "WorkPlane21" RotateAngle 0 ExtraOffset 0
work_plane "WorkPlane22" AlongDistance 75 (= "bodyWidth / 2") ExtraOffset 0
sketch "B End Cord Port" plane through (0, 0, 75) normal (0, 0, 1) x axis (1, 0, 0)
  line L1 (-125, 0) -> (0, 0)
  circle C1 centre (-125, 0) radius 2.25
  point P1 (0, 0)
  point P2 (-125, 0)
  horizontal L1
  dimension "d896" distance P1 P2 = 125 (= "abs(( 1 ) * ( ( -1 ) * cordStation ) + ( 0 ) * ( 0 mm ))")
  dimension "d897" diameter C1 = 4.5
extrude "Extrude42" cut sketch "B End Cord Port" profile of C1 no distance stored
chamfer "Chamfer4" distance 0.3 (= "bedRelief")
work_plane "WorkPlane23" RotateAngle 180 ExtraOffset 0
work_plane "WorkPlane24" AlongDistance 75 (= "bodyWidth / 2") ExtraOffset 0
sketch "B End Cord Port (1)" plane through (0, 0, -75) normal (0, 0, -1) x axis (-1, 0, 0)
  line L1 (125, 0) -> (0, 0)
  circle C1 centre (125, 0) radius 2.25
  point P1 (0, 0)
  point P2 (125, 0)
  horizontal L1
  dimension "d905" distance P1 P2 = 125 (= "abs(( -1 ) * ( ( -1 ) * cordStation ) + ( 0 ) * ( 0 mm ))")
  dimension "d906" diameter C1 = 4.5
extrude "Extrude43" cut sketch "B End Cord Port (1)" profile of C1 no distance stored
chamfer "Chamfer5" distance 0.3 (= "bedRelief")
work_plane "WorkPlane1" AlongDistance 22.6 (= "qRearBase") ExtraOffset 0
sketch "D Rear Holder Blank sketch" plane through (15.9806, 15.9806, 0) normal (0.7071, 0.7071, 0) x axis (0, 0, 1)
  circle C1 centre (0, 0) radius 22
  dimension "d912" diameter C1 = 44 (= "coreOD")
extrude "Extrude1" new body sketch "D Rear Holder Blank sketch" along normal blind 10.2 (= "shoulder + rearSeatDepth")
work_plane "WorkPlane2" AlongDistance 22.6 (= "qRearBase") ExtraOffset 0
sketch "D Seal Relief sketch" plane through (15.9806, 15.9806, 0) normal (0.7071, 0.7071, 0) x axis (0, 0, 1)
  circle C1 centre (0, 0) radius 9.75
  dimension "d917" diameter C1 = 19.5 (= "raceRelief")
extrude "Extrude2" cut sketch "D Seal Relief sketch" along normal blind 10.2 (= "shoulder + rearSeatDepth")
work_plane "WorkPlane3" AlongDistance 25.6 (= "qRearBearing") ExtraOffset 0
sketch "D Rear Bearing Seat sketch" plane through (18.1019, 18.1019, 0) normal (0.7071, 0.7071, 0) x axis (0, 0, 1)
  circle C1 centre (0, 0) radius 11.1
  dimension "d922" diameter C1 = 22.2 (= "seatDiameter")
extrude "Extrude3" cut sketch "D Rear Bearing Seat sketch" along normal blind 7.2 (= "rearSeatDepth")
work_plane "WorkPlane4" AlongDistance 22.6 (= "qRearBase") ExtraOffset 0
sketch "D Support Bolt seed" plane through (15.9806, 15.9806, 0) normal (0.7071, 0.7071, 0) x axis (0, 0, 1)
  line L1 (17, 0) -> (0, 0)
  circle C1 centre (17, 0) radius 1.65
  point P1 (0, 0)
  point P2 (17, 0)
  horizontal L1
  dimension "d927" distance P1 P2 = 17 (= "supportCircle / 2")
  dimension "d928" diameter C1 = 3.3 (= "m3Clearance")
extrude "Extrude4" cut sketch "D Support Bolt seed" profile of C1 along normal blind 10.2 (= "shoulder + rearSeatDepth")
circular_pattern "C-Pattern1" TotalAngle 360
chamfer "Chamfer1" distance 0.4 (= "entryChamfer")
chamfer "Chamfer2" distance 0.3 (= "bedRelief")
work_plane "WorkPlane1" AlongDistance -2.5 (= "qFront - capThickness") ExtraOffset 0
sketch "C Front Bearing Cap Ring sketch" plane through (-1.7678, -1.7678, 0) normal (0.7071, 0.7071, 0) x axis (0, 0, 1)
  circle C1 centre (0, 0) radius 22
  circle C2 centre (0, 0) radius 9.75
  dimension "d937" diameter C1 = 44 (= "coreOD")
  dimension "d938" diameter C2 = 19.5 (= "raceRelief")
extrude "Extrude1" new body sketch "C Front Bearing Cap Ring sketch" along normal blind 3 (= "capThickness")
work_plane "WorkPlane2" AlongDistance -2.5 (= "qFront - capThickness") ExtraOffset 0
sketch "C Front Bearing Cap Bolt seed" plane through (-1.7678, -1.7678, 0) normal (0.7071, 0.7071, 0) x axis (0, 0, 1)
  line L1 (17, 0) -> (0, 0)
  circle C1 centre (17, 0) radius 1.65
  point P1 (0, 0)
  point P2 (17, 0)
  horizontal L1
  dimension "d943" distance P1 P2 = 17 (= "supportCircle / 2")
  dimension "d944" diameter C1 = 3.3 (= "m3Clearance")
extrude "Extrude2" cut sketch "C Front Bearing Cap Bolt seed" profile of C1 along normal blind 3 (= "capThickness")
circular_pattern "C-Pattern1" TotalAngle 360
chamfer "Chamfer1" distance 0.3 (= "bedRelief")
work_plane "WorkPlane1" AlongDistance 32.8 (= "qRearEnd") ExtraOffset 0
sketch "E Rear Bearing Cap Ring sketch" plane through (23.1931, 23.1931, 0) normal (0.7071, 0.7071, 0) x axis (0, 0, 1)
  circle C1 centre (0, 0) radius 22
  circle C2 centre (0, 0) radius 9.75
  dimension "d952" diameter C1 = 44 (= "coreOD")
  dimension "d953" diameter C2 = 19.5 (= "raceRelief")
extrude "Extrude1" new body sketch "E Rear Bearing Cap Ring sketch" along normal blind 3 (= "capThickness")
work_plane "WorkPlane2" AlongDistance 32.8 (= "qRearEnd") ExtraOffset 0
sketch "E Rear Bearing Cap Bolt seed" plane through (23.1931, 23.1931, 0) normal (0.7071, 0.7071, 0) x axis (0, 0, 1)
  line L1 (17, 0) -> (0, 0)
  circle C1 centre (17, 0) radius 1.65
  point P1 (0, 0)
  point P2 (17, 0)
  horizontal L1
  dimension "d958" distance P1 P2 = 17 (= "supportCircle / 2")
  dimension "d959" diameter C1 = 3.3 (= "m3Clearance")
